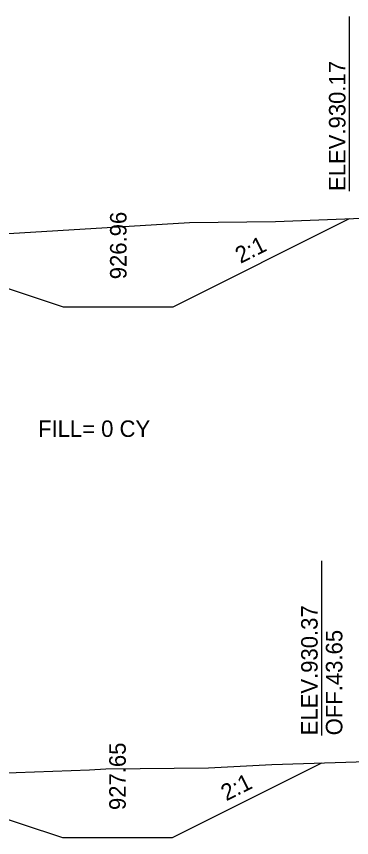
# Model space of a CAD drawing. Extents: x -4 to 359, y 0 to 1436.
# Drawn here: x 285.04 to 297.24, y 962.62 to 992.49 of the extents above; entities that cross this region are included whole.
import ezdxf

# ---------------------------------------------------------------- set-up
doc = ezdxf.new("R2010")
doc.units = 0
for name, color, linetype in [('XS-Existing surface-ground', 7, 'Continuous'), ('XS-Proposed surface-ground', 7, 'Continuous'), ('XS-Text-ditch slope', 7, 'Continuous'), ('XS-Text-earthwork labels', 7, 'Continuous'), ('XS-Text-profile report', 7, 'Continuous'), ('XS-Text-tie elevation', 7, 'Continuous'), ('XS-Text-tie offset', 7, 'Continuous')]:
    doc.layers.add(name, color=color, linetype=linetype)

msp = doc.modelspace()

# ---------------------------------------------------------------- linework, layer by layer
at = {"layer": 'XS-Existing surface-ground'}
for p, q in [((294.465, 985.036), (303.741, 985.392)), ((276.902, 984.125), (291.332, 984.998)), ((291.332, 984.998), (294.465, 985.036)), ((292.028, 965.165), (294.329, 965.286)), ((294.329, 965.286), (297.792, 965.395)), ((279.746, 964.8), (287.7, 965.084)), ((287.7, 965.084), (288.288, 965.12)), ((288.288, 965.12), (292.028, 965.165))]:
    msp.add_line(p, q, dxfattribs=at)
at = {"layer": 'XS-Proposed surface-ground'}
for points in [[(280.745, 983.91), (286.745, 981.93), (290.745, 981.93), (297.163, 985.14)], [(280.717, 964.606), (286.717, 962.626), (290.717, 962.626), (296.151, 965.343)]]:
    msp.add_lwpolyline(points, dxfattribs=at)
at = {"layer": 'XS-Text-tie offset'}
for p, q in [((297.163, 986.14), (297.163, 992.49)), ((296.151, 966.343), (296.151, 972.693))]:
    msp.add_line(p, q, dxfattribs=at)

# ---------------------------------------------------------------- texts
at = {"layer": 'XS-Text-ditch slope'}
for p in [(293.194, 983.49), (292.674, 963.94)]:
    msp.add_text('2:1', height=0.6, rotation=26.5651, dxfattribs=at).set_placement(p)
at = {"layer": 'XS-Text-earthwork labels'}
msp.add_text('FILL= 0 CY           ', height=0.6, dxfattribs=at).set_placement((285.826, 977.196))
at = {"layer": 'XS-Text-profile report'}
for s, p in [('Dtch_Bkslp_1_T', (297.152, 985.139)), ('Dtch_Frslp_1_B', (286.734, 981.93)), ('Dtch_Bkslp_1_B', (290.734, 981.93)), ('Dtch_Bkslp_1_T', (296.14, 965.342)), ('Dtch_Frslp_1_B', (286.705, 962.625)), ('Dtch_Bkslp_1_B', (290.705, 962.625))]:
    msp.add_text(s, height=0.00167, dxfattribs=at).set_placement(p)
at = {"layer": 'XS-Text-tie elevation'}
for s, p in [('ELEV.930.17', (297.013, 986.14)), ('926.96', (289.045, 982.93)), ('ELEV.930.37', (296.001, 966.343)), ('OFF.43.65', (296.901, 966.343)), ('927.65', (289.017, 963.626))]:
    msp.add_text(s, height=0.6, rotation=90, dxfattribs=at).set_placement(p)

doc.saveas('drawing.dxf')
